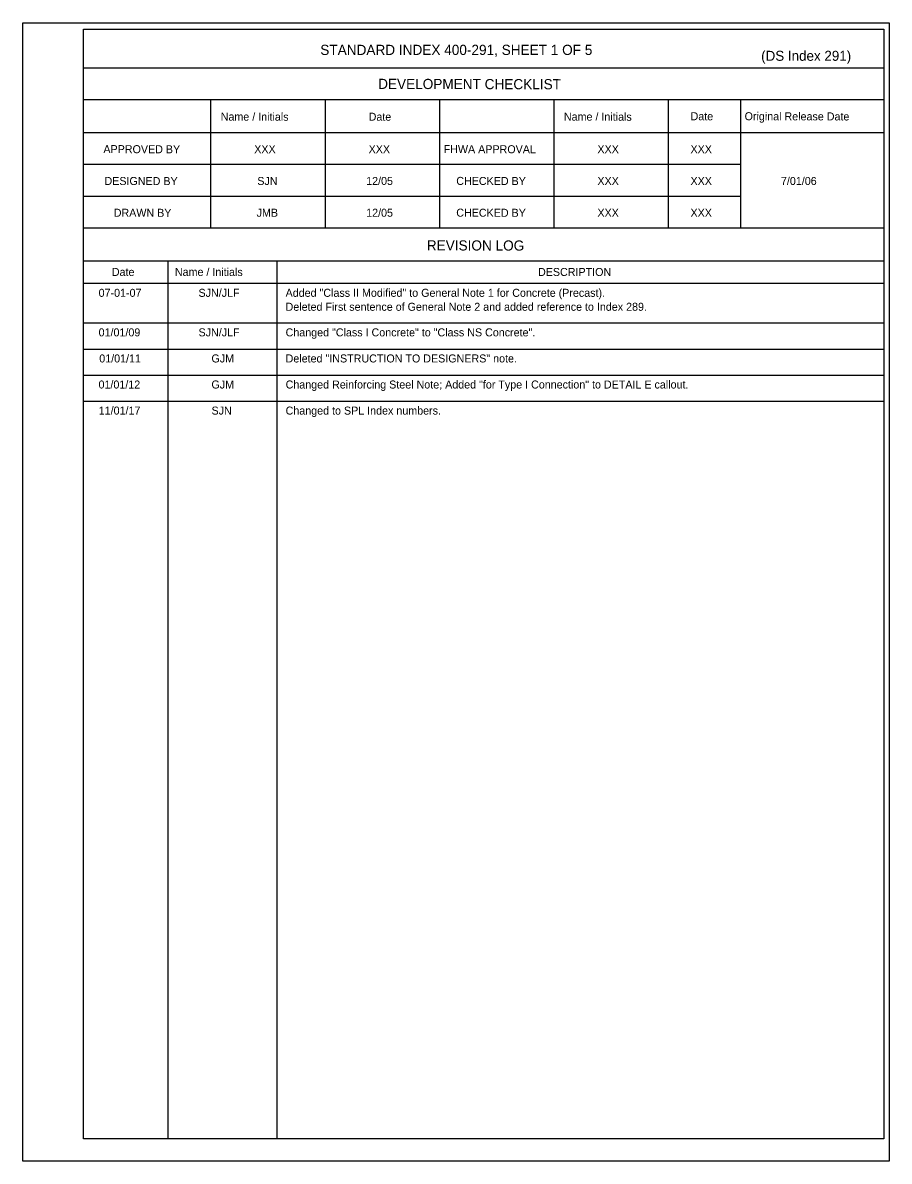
# Model space of a CAD drawing. Extents: x 10050 to 10414, y 76434 to 76519.
# Drawn here: x 10362 to 10414.4, y 76446.3 to 76515.1 of the extents above; entities that cross this region are included whole.
import ezdxf

# ---------------------------------------------------------------- set-up
doc = ezdxf.new("R2010")
doc.units = 0
for name, color, linetype in [('Border', 7, 'Continuous'), ('Patterning', 7, 'Continuous'), ('PlotBorder_dp', 7, 'Continuous'), ('SheetLines_dp', 7, 'Continuous')]:
    doc.layers.add(name, color=color, linetype=linetype)

msp = doc.modelspace()

# ---------------------------------------------------------------- linework, layer by layer
at = {"layer": 'Border'}
for p, q in [((10414.043, 76512.338), (10365.69, 76512.338)), ((10414.043, 76510.418), (10365.69, 76510.418)), ((10373.37, 76510.418), (10373.37, 76502.671)), ((10380.282, 76510.418), (10380.282, 76502.671)), ((10387.194, 76510.418), (10387.194, 76502.671)), ((10394.106, 76510.418), (10394.106, 76502.671)), ((10401.018, 76510.418), (10401.018, 76502.671)), ((10405.374, 76510.418), (10405.374, 76502.671)), ((10414.043, 76508.431), (10365.69, 76508.431)), ((10405.374, 76506.511), (10365.69, 76506.511)), ((10405.374, 76504.591), (10365.69, 76504.591)), ((10414.043, 76502.671), (10365.69, 76502.671)), ((10414.043, 76500.684), (10365.69, 76500.684)), ((10370.779, 76500.684), (10370.779, 76447.628)), ((10377.361, 76500.684), (10377.361, 76447.628)), ((10414.043, 76499.331), (10365.69, 76499.331))]:
    msp.add_line(p, q, dxfattribs=at)
msp.add_lwpolyline([(10365.691, 76514.691), (10414.043, 76514.691), (10414.043, 76447.628), (10365.691, 76447.628)], close=True, dxfattribs=at)
at = {"layer": 'Patterning'}
for p, q in [((10365.691, 76496.94), (10414.043, 76496.94)), ((10365.691, 76495.364), (10414.043, 76495.364)), ((10365.691, 76493.789), (10414.043, 76493.789)), ((10365.691, 76492.213), (10414.043, 76492.213))]:
    msp.add_line(p, q, dxfattribs=at)
at = {"layer": 'PlotBorder_dp'}
msp.add_line((10362.017, 76446.281), (10362.017, 76446.281), dxfattribs=at)
msp.add_lwpolyline([(10362.017, 76515.081), (10414.369, 76515.081), (10414.369, 76446.281), (10362.017, 76446.281)], close=True, dxfattribs=at)

# ---------------------------------------------------------------- texts
at = {"layer": 'Patterning'}
msp.add_text('(DS Index 291)', height=0.6048, dxfattribs=at).set_placement((10406.631, 76512.782))
at = {"layer": 'SheetLines_dp'}
for s, height, p in [('STANDARD INDEX 400-291, SHEET 1 OF 5', 0.6144, (10379.995, 76513.136)), ('XXX', 0.4838, (10376.002, 76507.199)), ('XXX', 0.4838, (10382.914, 76507.199)), ('XXX', 0.4838, (10396.738, 76507.199)), ('XXX', 0.4838, (10402.362, 76507.199)), ('SJN', 0.4838, (10376.188, 76505.279)), ('12/05', 0.4838, (10382.766, 76505.279)), ('XXX', 0.4838, (10396.738, 76505.279)), ('XXX', 0.4838, (10402.362, 76505.279)), ('7/01/06', 0.4838, (10407.827, 76505.279)), ('JMB', 0.4838, (10376.147, 76503.359)), ('12/05', 0.4838, (10382.766, 76503.359)), ('XXX', 0.4838, (10396.738, 76503.359)), ('XXX', 0.4838, (10402.362, 76503.359)), ('DESCRIPTION', 0.48384, (10393.149, 76499.779)), ('07-01-07', 0.4838, (10366.6, 76498.519)), ('SJN/JLF', 0.4838, (10372.636, 76498.519)), ('Added "Class II Modified" to General Note 1 for Concrete (Precast).', 0.48384, (10377.897, 76498.519)), ('Deleted First sentence of General Note 2 and added reference to Index 289.', 0.48384, (10377.897, 76497.676)), ('01/01/09', 0.4838, (10366.6, 76496.129)), ('SJN/JLF', 0.4838, (10372.637, 76496.129)), ('Changed "Class I Concrete" to "Class NS Concrete".', 0.48384, (10377.898, 76496.129)), ('01/01/11', 0.4838, (10366.639, 76494.553)), ('GJM', 0.4838, (10373.418, 76494.553)), ('Deleted "INSTRUCTION TO DESIGNERS" note.', 0.48384, (10377.898, 76494.553)), ('01/01/12', 0.4838, (10366.595, 76492.978)), ('GJM', 0.4838, (10373.418, 76492.978)), ('Changed Reinforcing Steel Note; Added "for Type I Connection" to DETAIL E callout.', 0.48384, (10377.898, 76492.978)), ('11/01/17', 0.4838, (10366.606, 76491.402)), ('SJN', 0.4838, (10373.422, 76491.402)), ('Changed to SPL Index numbers.', 0.48384, (10377.898, 76491.402))]:
    msp.add_text(s, height=height, dxfattribs=at).set_placement(p)
for s, height, p in [('DEVELOPMENT CHECKLIST', 0.6144, (10383.488, 76511.082)), ('Name / Initials', 0.48384, (10373.977, 76509.168)), ('Date', 0.4838, (10382.915, 76509.163)), ('Name / Initials', 0.48384, (10394.713, 76509.168)), ('Date', 0.4838, (10402.367, 76509.191)), ('Original Release Date', 0.48384, (10405.631, 76509.191)), ('APPROVED BY', 0.48384, (10366.889, 76507.203)), ('FHWA APPROVAL', 0.48384, (10387.447, 76507.204)), ('DESIGNED BY', 0.48384, (10366.953, 76505.28)), ('CHECKED BY', 0.4838, (10388.209, 76505.283)), ('DRAWN BY', 0.4838, (10367.514, 76503.36)), ('CHECKED BY', 0.4838, (10388.209, 76503.363)), ('REVISION LOG', 0.6144, (10386.429, 76501.324)), ('Date', 0.4838, (10367.4, 76499.781)), ('Name / Initials', 0.48384, (10371.208, 76499.785))]:
    msp.add_text(s, height=height, rotation=359.87563, dxfattribs=at).set_placement(p)

doc.saveas('drawing.dxf')
